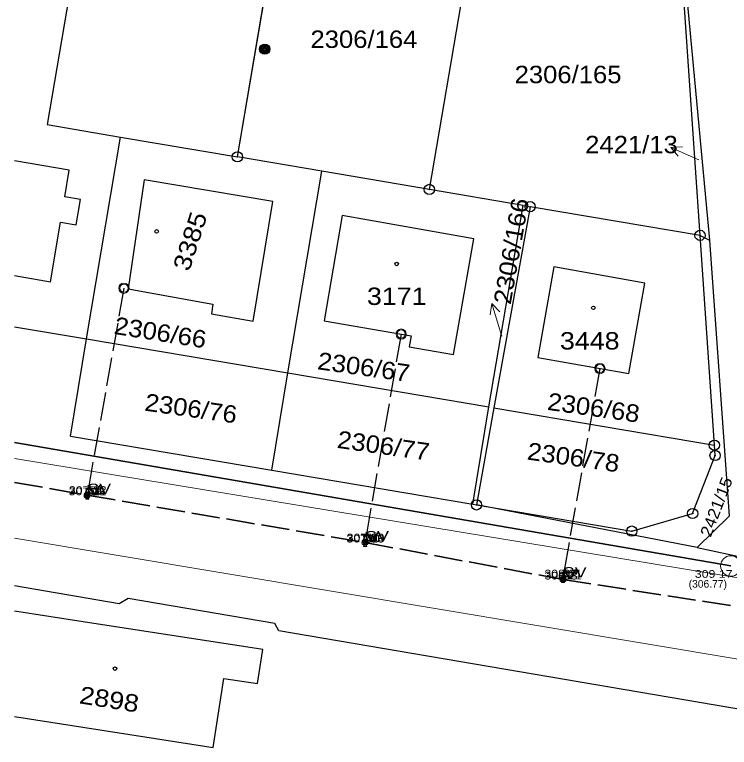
# Model space of a CAD drawing. Extents: x -652394 to -652006, y -1024262 to -1023975.
# Drawn here: x -652393.6 to -652323.8, y -1024118.2 to -1024046.7 of the extents above; entities that cross this region are included whole.
import ezdxf
from ezdxf.enums import TextEntityAlignment as Align

# ---------------------------------------------------------------- set-up
doc = ezdxf.new("R2010")
doc.units = 0
doc.header["$LTSCALE"] = 0.46
doc.header["$PDMODE"] = 32
doc.header["$PDSIZE"] = 0.23
doc.linetypes.add('LONG_DASHED', pattern=[7.5, 6, -1.5])
for name, color, linetype in [('1', 7, 'Continuous'), ('2', 7, 'Continuous'), ('3', 7, 'Continuous'), ('4', 7, 'Continuous')]:
    doc.layers.add(name, color=color, linetype=linetype)
for name, color, linetype, lineweight in [('10', 7, 'Continuous', 13), ('12', 7, 'Continuous', 13), ('35', 7, 'LONG_DASHED', 35), ('45', 7, 'Continuous', 35), ('50', 7, 'LONG_DASHED', 25), ('63', 7, 'Continuous', 25)]:
    doc.layers.add(name, color=color, linetype=linetype, lineweight=lineweight)

msp = doc.modelspace()

# ---------------------------------------------------------------- linework, layer by layer
at = {"layer": '1'}
for p in [(-652386.48, -1024093.56), (-652386.46, -1024093.43), (-652359.37, -1024098.17), (-652359.35, -1024098.06), (-652340.06, -1024101.58), (-652340.06, -1024101.78)]:
    msp.add_point(p, dxfattribs=at)
at = {"layer": '10'}
for points in [[(-652386.31, -1024093.93), (-652386.61, -1024092.93), (-652386.31, -1024092.93), (-652386.61, -1024093.93)], [(-652359.2, -1024098.56), (-652359.5, -1024097.56), (-652359.2, -1024097.56), (-652359.5, -1024098.56)], [(-652339.91, -1024102.08), (-652340.21, -1024101.08), (-652339.91, -1024101.08), (-652340.21, -1024102.08)]]:
    msp.add_lwpolyline(points, close=True, dxfattribs=at)
msp.add_circle((-652323.67, -1024100.461), 1.0002, dxfattribs=at)
at = {"layer": '12'}
for centre, radius in [((-652382.892, -1024073.358), 0.5), ((-652382.892, -1024073.358), 0.4), ((-652355.843, -1024077.831), 0.5), ((-652355.843, -1024077.831), 0.4), ((-652336.447, -1024081.193), 0.5), ((-652336.447, -1024081.193), 0.4), ((-652386.48, -1024093.56), 0.3), ((-652386.48, -1024093.56), 0.2), ((-652386.48, -1024093.56), 0.1), ((-652359.37, -1024098.17), 0.3), ((-652359.37, -1024098.17), 0.2), ((-652359.37, -1024098.17), 0.1), ((-652340.06, -1024101.78), 0.3), ((-652340.06, -1024101.78), 0.2), ((-652340.06, -1024101.78), 0.1)]:
    msp.add_circle(centre, radius, dxfattribs=at)
at = {"layer": '35'}
for p, q in [((-652393.553, -1024092.3), (-652386.48, -1024093.56)), ((-652386.48, -1024093.56), (-652359.37, -1024098.17)), ((-652359.37, -1024098.17), (-652340.06, -1024101.78)), ((-652340.06, -1024101.78), (-652319.053, -1024105.044))]:
    msp.add_line(p, q, dxfattribs=at)
at = {"layer": '45'}
msp.add_line((-652323.67, -1024100.46), (-652393.553, -1024088.403), dxfattribs=at)
at = {"layer": '50'}
for p, q in [((-652382.892, -1024073.358), (-652386.46, -1024093.43)), ((-652355.843, -1024077.831), (-652359.35, -1024098.06)), ((-652336.447, -1024081.193), (-652340.06, -1024101.58)), ((-652386.46, -1024093.43), (-652386.48, -1024093.56)), ((-652359.35, -1024098.06), (-652359.37, -1024098.17)), ((-652340.06, -1024101.58), (-652340.06, -1024101.78))]:
    msp.add_line(p, q, dxfattribs=at)
at = {"layer": '63'}
for p, q in [((-652371.82, -1024060.54), (-652365.1, -1024021.22)), ((-652386.53, -1024034.83), (-652390.39, -1024057.39)), ((-652390.39, -1024057.39), (-652383.22, -1024058.61)), ((-652363.58, -1024061.94), (-652371.82, -1024060.54)), ((-652366.91, -1024081.62), (-652363.58, -1024061.94)), ((-652343.94, -1024065.27), (-652343.25, -1024065.4)), ((-652326.68, -1024068.2), (-652325.76, -1024068.66)), ((-652393.553, -1024077.11), (-652386.54, -1024078.3)), ((-652388.1, -1024087.8), (-652386.54, -1024078.3)), ((-652386.54, -1024078.3), (-652366.91, -1024081.62)), ((-652348.85, -1024094.44), (-652347.29, -1024084.94)), ((-652346.8, -1024085.02), (-652348.49, -1024094.5)), ((-652346.8, -1024085.02), (-652325.28, -1024088.67)), ((-652388.1, -1024087.8), (-652368.47, -1024091.12)), ((-652368.47, -1024091.12), (-652348.85, -1024094.44)), ((-652348.85, -1024094.44), (-652348.49, -1024094.5)), ((-652326.97, -1024098.66), (-652348.49, -1024094.5)), ((-652326.97, -1024098.66), (-652320.26, -1024100.1))]:
    msp.add_line(p, q, dxfattribs=at)
at = {"layer": '63', "lineweight": 13}
for p, q in [((-652329.522, -1024059.619), (-652328.81, -1024060.484)), ((-652346.977, -1024074.86), (-652347.163, -1024075.964)), ((-652346.01, -1024078.03), (-652346.1, -1024077.73)), ((-652393.553, -1024089.984), (-652320.54, -1024102.03)), ((-652393.553, -1024097.734), (-652321.66, -1024109.76))]:
    msp.add_line(p, q, dxfattribs=at)
for points in [[(-652386.53, -1024034.83), (-652390.39, -1024057.39), (-652383.22, -1024058.61), (-652371.82, -1024060.54), (-652365.1, -1024021.22), (-652383.67, -1024018.07), (-652385.33, -1024027.79)], [(-652346.36, -1024024.39), (-652365.1, -1024021.22), (-652371.82, -1024060.54), (-652363.58, -1024061.94), (-652353.09, -1024063.72)], [(-652329.11, -1024032.73), (-652330.91, -1024027.84), (-652334.88, -1024026.34), (-652346.36, -1024024.39), (-652353.09, -1024063.72), (-652343.94, -1024065.27), (-652343.25, -1024065.4), (-652326.68, -1024068.2)], [(-652325.76, -1024068.66), (-652328.05, -1024043.94), (-652329.29, -1024030.08), (-652330.91, -1024027.84), (-652329.11, -1024032.73), (-652326.68, -1024068.2)], [(-652366.91, -1024081.62), (-652363.58, -1024061.94), (-652371.82, -1024060.54), (-652383.22, -1024058.61), (-652386.54, -1024078.3)], [(-652353.09, -1024063.72), (-652363.58, -1024061.94), (-652366.91, -1024081.62), (-652347.29, -1024084.94), (-652343.94, -1024065.27)], [(-652374.22, -1024074.9), (-652374.35, -1024075.86), (-652370.29, -1024076.56), (-652368.35, -1024064.88), (-652380.93, -1024062.78), (-652382.49, -1024073.43)], [(-652374.22, -1024074.9), (-652382.49, -1024073.43), (-652380.93, -1024062.78), (-652368.35, -1024064.88), (-652370.29, -1024076.56), (-652374.35, -1024075.86)], [(-652382.49, -1024073.43), (-652374.22, -1024074.9), (-652374.35, -1024075.86), (-652370.29, -1024076.56), (-652368.35, -1024064.88), (-652380.93, -1024062.78)], [(-652348.49, -1024094.5), (-652346.8, -1024085.02), (-652343.25, -1024065.4), (-652343.94, -1024065.27), (-652347.29, -1024084.94), (-652348.85, -1024094.44)], [(-652325.28, -1024088.67), (-652326.68, -1024068.2), (-652343.25, -1024065.4), (-652346.8, -1024085.02)], [(-652354.87, -1024078), (-652355.06, -1024079.08), (-652350.73, -1024079.83), (-652348.75, -1024068.54), (-652361.58, -1024066.27), (-652363.35, -1024076.53)], [(-652354.87, -1024078), (-652363.35, -1024076.53), (-652361.58, -1024066.27), (-652348.75, -1024068.54), (-652350.73, -1024079.83), (-652355.06, -1024079.08)], [(-652363.35, -1024076.53), (-652354.87, -1024078), (-652355.06, -1024079.08), (-652350.73, -1024079.83), (-652348.75, -1024068.54), (-652361.58, -1024066.27)], [(-652326.97, -1024098.66), (-652323.85, -1024095.61), (-652325.76, -1024068.66), (-652326.68, -1024068.2), (-652325.28, -1024088.67), (-652325.21, -1024089.68), (-652327.4, -1024095.34), (-652333.34, -1024097.06), (-652348.49, -1024094.5)], [(-652340.94, -1024071.26), (-652332.05, -1024072.85), (-652333.64, -1024081.69), (-652342.5, -1024080.12)], [(-652340.94, -1024071.26), (-652342.5, -1024080.12), (-652333.64, -1024081.69), (-652332.05, -1024072.85)], [(-652333.64, -1024081.69), (-652332.05, -1024072.85), (-652340.94, -1024071.26), (-652342.5, -1024080.12)], [(-652366.91, -1024081.62), (-652386.54, -1024078.3), (-652388.1, -1024087.8), (-652368.47, -1024091.12)], [(-652348.85, -1024094.44), (-652347.29, -1024084.94), (-652366.91, -1024081.62), (-652368.47, -1024091.12)], [(-652333.34, -1024097.06), (-652327.4, -1024095.34), (-652325.21, -1024089.68), (-652325.28, -1024088.67), (-652346.8, -1024085.02), (-652348.49, -1024094.5)]]:
    msp.add_lwpolyline(points, close=True, dxfattribs=at)
at = {"layer": '63'}
for points in [[(-652353.09, -1024063.72), (-652346.36, -1024024.39), (-652365.1, -1024021.22)], [(-652330.91, -1024027.84), (-652329.29, -1024030.08), (-652328.05, -1024043.94), (-652325.76, -1024068.66)], [(-652326.68, -1024068.2), (-652329.11, -1024032.73), (-652330.91, -1024027.84)], [(-652386.54, -1024078.3), (-652383.22, -1024058.61), (-652371.82, -1024060.54)], [(-652393.553, -1024072.111), (-652390.06, -1024072.72), (-652389.08, -1024066.91), (-652387.55, -1024067.17), (-652387.13, -1024064.71), (-652388.66, -1024064.45), (-652388.22, -1024061.84), (-652393.553, -1024060.916)], [(-652347.29, -1024084.94), (-652343.94, -1024065.27), (-652353.09, -1024063.72), (-652363.58, -1024061.94)], [(-652325.28, -1024088.67), (-652326.68, -1024068.2), (-652343.25, -1024065.4), (-652346.8, -1024085.02)], [(-652325.76, -1024068.66), (-652323.85, -1024095.61), (-652326.97, -1024098.66)], [(-652368.47, -1024091.12), (-652366.91, -1024081.62), (-652347.29, -1024084.94)], [(-652348.49, -1024094.5), (-652333.34, -1024097.06), (-652327.4, -1024095.34), (-652325.21, -1024089.68), (-652325.28, -1024088.67)], [(-652322.35, -1024114.53), (-652367.79, -1024106.79), (-652368.18, -1024106.06), (-652382.49, -1024103.63), (-652383.34, -1024104.14), (-652393.553, -1024102.4)], [(-652369.87, -1024111.94), (-652369.35, -1024108.61), (-652386.86, -1024105.9), (-652393.553, -1024104.865)], [(-652393.553, -1024115.158), (-652374.17, -1024118.16), (-652373.13, -1024111.43), (-652369.87, -1024111.94)]]:
    msp.add_lwpolyline(points, dxfattribs=at)
at = {"layer": '63', "lineweight": 13}
for points in [[(-652326.78, -1024060.84), (-652329.522, -1024059.619), (-652328.403, -1024059.569)], [(-652346.1, -1024077.73), (-652346.977, -1024074.86), (-652346.206, -1024075.671)]]:
    msp.add_lwpolyline(points, dxfattribs=at)
at = {"layer": '63'}
for points in [[(-652374.22, -1024074.9), (-652374.35, -1024075.86), (-652370.29, -1024076.56), (-652368.35, -1024064.88), (-652380.93, -1024062.78), (-652382.49, -1024073.43)], [(-652354.87, -1024078), (-652355.06, -1024079.08), (-652350.73, -1024079.83), (-652348.75, -1024068.54), (-652361.58, -1024066.27), (-652363.35, -1024076.53)], [(-652340.94, -1024071.26), (-652342.5, -1024080.12), (-652333.64, -1024081.69), (-652332.05, -1024072.85)]]:
    msp.add_lwpolyline(points, close=True, dxfattribs=at)
for centre, radius in [((-652369.1534, -1024050.0299), 0.5), ((-652369.1534, -1024050.0299), 0.4), ((-652369.1534, -1024050.0299), 0.3), ((-652369.1534, -1024050.0299), 0.2), ((-652369.1534, -1024050.0299), 0.1), ((-652371.82, -1024060.5399), 0.5), ((-652371.82, -1024060.5399), 0.0303), ((-652353.09, -1024063.7199), 0.5), ((-652353.09, -1024063.7199), 0.0303), ((-652343.25, -1024065.3999), 0.5), ((-652343.25, -1024065.3999), 0.0303), ((-652379.6968, -1024067.8192), 0.175), ((-652326.68, -1024068.1999), 0.5), ((-652326.68, -1024068.1999), 0.0303), ((-652356.2768, -1024070.9892), 0.175), ((-652337.0868, -1024075.2692), 0.175), ((-652325.28, -1024088.6699), 0.5), ((-652325.21, -1024089.6799), 0.5), ((-652325.28, -1024088.6699), 0.0303), ((-652325.21, -1024089.6799), 0.0303), ((-652348.49, -1024094.4999), 0.5), ((-652348.49, -1024094.4999), 0.0303), ((-652327.4, -1024095.3399), 0.5), ((-652327.4, -1024095.3399), 0.0303), ((-652333.34, -1024097.0599), 0.5), ((-652333.34, -1024097.0599), 0.0303), ((-652383.7568, -1024110.4792), 0.175)]:
    msp.add_circle(centre, radius, dxfattribs=at)

# ---------------------------------------------------------------- texts
at = {"layer": '2', "width": 1.3}
for s, p in [('59', (-652386.48, -1024093.56)), ('58', (-652386.46, -1024093.43)), ('60', (-652359.37, -1024098.17)), ('61', (-652359.35, -1024098.06)), ('62', (-652340.06, -1024101.58)), ('63', (-652340.06, -1024101.78))]:
    msp.add_text(s, height=0.75, dxfattribs=at).set_placement(p)
at = {"layer": '3', "width": 1.2}
for s, p in [('307 31 ', (-652386.278, -1024093.56)), ('307 32 ', (-652386.258, -1024093.43)), ('307 88 ', (-652359.168, -1024098.17)), ('307 90 ', (-652359.148, -1024098.06)), ('308 21 ', (-652339.858, -1024101.58)), ('308 21 ', (-652339.858, -1024101.78)), ('309 17 ', (-652325.179, -1024101.615))]:
    msp.add_text(s, height=0.75, dxfattribs=at).set_placement(p, align=Align.CENTER)
at = {"layer": '3'}
msp.add_text('(306.77)', height=0.75, dxfattribs=at).set_placement((-652325.917, -1024102.581), align=Align.CENTER)
at = {"layer": '4'}
for s, width, p in [('V', 1.55, (-652386.48, -1024093.56)), ('SV', 1.3, (-652386.46, -1024093.43)), ('SV', 1.3, (-652359.35, -1024098.06)), ('V', 1.55, (-652359.37, -1024098.17)), ('SV', 1.3, (-652340.06, -1024101.58)), ('V', 1.55, (-652340.06, -1024101.78))]:
    msp.add_text(s, height=1, dxfattribs=dict(at, width=width)).set_placement(p)
at = {"layer": '63'}
for s, width, p in [('2306/164', 1.1, (-652364.69, -1024049.91)), ('2306/165', 1.1, (-652344.77, -1024053.35)), ('2421/13', 1.1, (-652337.886, -1024060.19)), ('3171', 1.15, (-652359.177, -1024074.99)), ('3448', 1.15, (-652340.347, -1024079.34))]:
    msp.add_text(s, height=1.7, dxfattribs=dict(at, width=width)).set_placement(p)
for s, height, rotation, width, p in [('2306/166', 1.7, 80, 1.1, (-652345.162, -1024075.017)), ('3385', 1.7, 72, 1.15, (-652376.526, -1024071.797)), ('2306/66', 1.7, 351, 1.1, (-652383.933, -1024077.809)), ('2306/67', 1.7, 352, 1.1, (-652364.079, -1024081.257)), ('2306/76', 1.7, 352, 1.1, (-652380.939, -1024085.297)), ('2306/68', 1.7, 352, 1.1, (-652341.649, -1024085.217)), ('2306/77', 1.7, 352, 1.1, (-652362.159, -1024088.927)), ('2306/78', 1.7, 352, 1.1, (-652343.619, -1024090.067)), ('2421/15', 1.139, 69, 1.1, (-652325.638, -1024097.724)), ('2898', 1.7, 351, 1.15, (-652387.319, -1024113.857))]:
    msp.add_text(s, height=height, rotation=rotation, dxfattribs=dict(at, width=width)).set_placement(p)

doc.saveas('drawing.dxf')
